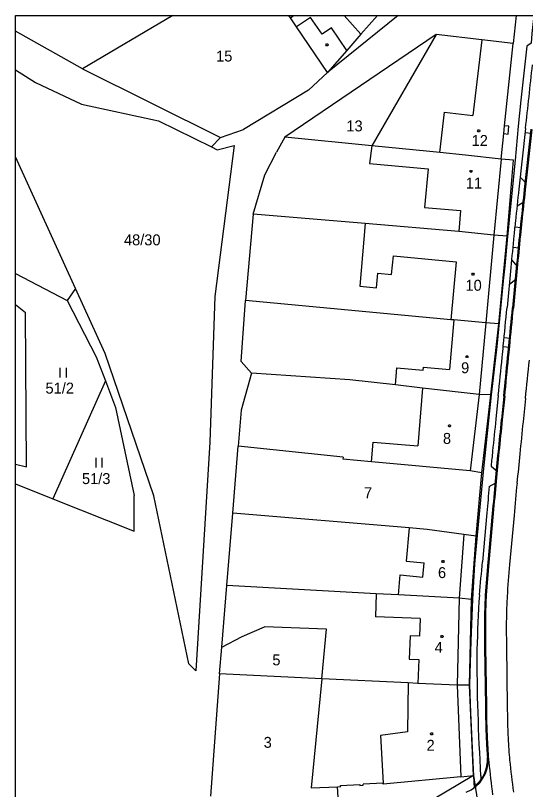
# Model space of a CAD drawing. Extents: x -639590 to -639298, y -1193269 to -1192863.
# Drawn here: x -639590.4 to -639511.2, y -1192983.6 to -1192863.3 of the extents above; entities that cross this region are included whole.
import ezdxf

# ---------------------------------------------------------------- set-up
doc = ezdxf.new("R2010")
doc.units = 0
for name, color, linetype in [('Vrstva 1', 7, 'Continuous'), ('Vrstva 19', 7, 'Continuous'), ('Vrstva 2', 7, 'Continuous'), ('Vrstva 20', 7, 'Continuous'), ('Vrstva 21', 7, 'Continuous'), ('Vrstva 3', 7, 'Continuous'), ('Vrstva 4', 7, 'Continuous'), ('Vrstva 5', 7, 'Continuous'), ('Vrstva 61', 7, 'Continuous')]:
    doc.layers.add(name, color=color, linetype=linetype)

msp = doc.modelspace()

# ---------------------------------------------------------------- linework, layer by layer
at = {"layer": 'Vrstva 1'}
for p, q in [((-639565.97, -1192863.27), (-639580, -1192871.57)), ((-639547.69, -1192863.63), (-639547.93, -1192863.27)), ((-639546.73, -1192865.04), (-639547.69, -1192863.63)), ((-639530.97, -1192863.27), (-639541.93, -1192872.12)), ((-639534.19, -1192863.27), (-639536.75, -1192866.15)), ((-639512.63, -1192863.27), (-639513.1, -1192867.65)), ((-639541.93, -1192872.12), (-639546.73, -1192865.04)), ((-639580, -1192871.57), (-639590.39, -1192865.7)), ((-639525.06, -1192866.23), (-639548.56, -1192882.19)), ((-639536.75, -1192866.15), (-639538.95, -1192868.69)), ((-639525.06, -1192866.23), (-639535.07, -1192883.53)), ((-639517.99, -1192867.05), (-639525.06, -1192866.23)), ((-639513.1, -1192867.65), (-639517.99, -1192867.05)), ((-639514.43, -1192880.41), (-639513.1, -1192867.65)), ((-639538.95, -1192868.69), (-639541.93, -1192872.12)), ((-639580, -1192871.57), (-639558.56, -1192882.23)), ((-639590.39, -1192871.73), (-639587.31, -1192873.7)), ((-639541.93, -1192872.12), (-639544.9, -1192874.86)), ((-639587.31, -1192873.7), (-639580.13, -1192877.06)), ((-639544.9, -1192874.86), (-639555, -1192880.97)), ((-639580.13, -1192877.06), (-639568.16, -1192879.64)), ((-639568.16, -1192879.64), (-639559.97, -1192883.7)), ((-639558.56, -1192882.23), (-639555, -1192880.97)), ((-639513.76, -1192880.48), (-639514.43, -1192880.41)), ((-639513.89, -1192881.71), (-639513.76, -1192880.48)), ((-639559.97, -1192883.7), (-639558.56, -1192882.23)), ((-639548.56, -1192882.19), (-639549.88, -1192884.53)), ((-639535.07, -1192883.53), (-639548.56, -1192882.19)), ((-639514.97, -1192885.59), (-639514.56, -1192881.64)), ((-639514.56, -1192881.64), (-639513.89, -1192881.71)), ((-639556.45, -1192883.48), (-639559.45, -1192906.94)), ((-639559.07, -1192884.15), (-639556.45, -1192883.48)), ((-639526.07, -1192884.42), (-639535.07, -1192883.53)), ((-639559.97, -1192883.7), (-639559.07, -1192884.15)), ((-639551.68, -1192888.03), (-639549.88, -1192884.53)), ((-639524.51, -1192884.57), (-639526.07, -1192884.42)), ((-639520.5, -1192884.97), (-639524.51, -1192884.57)), ((-639581.05, -1192905.73), (-639590.39, -1192885.22)), ((-639514.97, -1192885.59), (-639520.5, -1192884.97)), ((-639513.07, -1192885.76), (-639514.97, -1192885.59)), ((-639514.06, -1192897.59), (-639513.07, -1192885.76)), ((-639553.46, -1192894.18), (-639551.68, -1192888.03)), ((-639553.46, -1192894.18), (-639554.66, -1192907.58)), ((-639536.07, -1192895.63), (-639553.46, -1192894.18)), ((-639521.55, -1192896.85), (-639536.07, -1192895.63)), ((-639516.13, -1192897.41), (-639521.55, -1192896.85)), ((-639514.06, -1192897.59), (-639516.13, -1192897.41)), ((-639515.33, -1192911.2), (-639514.06, -1192897.59)), ((-639590.39, -1192903.36), (-639582.38, -1192907.56)), ((-639581.05, -1192905.73), (-639582.38, -1192907.56)), ((-639576.45, -1192915.83), (-639581.05, -1192905.73)), ((-639582.38, -1192907.56), (-639577.84, -1192916.35)), ((-639559.45, -1192906.94), (-639560.22, -1192929.6)), ((-639555.33, -1192917.06), (-639554.66, -1192907.58)), ((-639522.8, -1192910.56), (-639554.66, -1192907.58)), ((-639590.39, -1192908.18), (-639588.84, -1192909.43)), ((-639588.7, -1192933.43), (-639588.84, -1192909.43)), ((-639522.3, -1192910.61), (-639522.8, -1192910.56)), ((-639517.37, -1192911.07), (-639522.3, -1192910.61)), ((-639515.33, -1192911.2), (-639517.37, -1192911.07)), ((-639516.56, -1192922.27), (-639515.33, -1192911.2)), ((-639568.92, -1192937.95), (-639576.45, -1192915.83)), ((-639577.84, -1192916.35), (-639576.43, -1192920.08)), ((-639553.74, -1192918.86), (-639555.33, -1192917.06)), ((-639553.74, -1192918.86), (-639555.36, -1192924.62)), ((-639538.45, -1192919.9), (-639553.74, -1192918.86)), ((-639576.43, -1192920.08), (-639584.61, -1192938.41)), ((-639576.43, -1192920.08), (-639574.87, -1192924.21)), ((-639531.39, -1192920.71), (-639538.45, -1192919.9)), ((-639527.16, -1192921.19), (-639531.39, -1192920.71)), ((-639518.37, -1192922.19), (-639527.16, -1192921.19)), ((-639516.56, -1192922.27), (-639518.37, -1192922.19)), ((-639517.98, -1192934.38), (-639516.56, -1192922.27)), ((-639574.87, -1192924.21), (-639571.95, -1192937.9)), ((-639555.36, -1192924.62), (-639555.81, -1192930.2)), ((-639560.22, -1192929.6), (-639562.4, -1192965.13)), ((-639556.66, -1192940.65), (-639555.81, -1192930.2)), ((-639539.5, -1192931.94), (-639555.81, -1192930.2)), ((-639539.5, -1192931.94), (-639539.53, -1192932.24)), ((-639535.12, -1192932.64), (-639539.53, -1192932.24)), ((-639519.77, -1192934.05), (-639535.12, -1192932.64)), ((-639590.39, -1192933.02), (-639588.7, -1192933.43)), ((-639517.98, -1192934.38), (-639519.77, -1192934.05)), ((-639518.83, -1192944.22), (-639517.98, -1192934.38)), ((-639590.39, -1192936.1), (-639584.61, -1192938.41)), ((-639584.61, -1192938.41), (-639571.98, -1192943.45)), ((-639571.98, -1192943.45), (-639571.95, -1192937.9)), ((-639563.48, -1192964.08), (-639568.92, -1192937.95)), ((-639557.57, -1192951.91), (-639556.66, -1192940.65)), ((-639529.25, -1192942.94), (-639556.66, -1192940.65)), ((-639526.45, -1192943.17), (-639529.25, -1192942.94)), ((-639520.79, -1192943.95), (-639526.45, -1192943.17)), ((-639518.83, -1192944.22), (-639520.79, -1192943.95)), ((-639519.57, -1192954.08), (-639518.83, -1192944.22)), ((-639558.35, -1192961.49), (-639557.57, -1192951.91)), ((-639534.37, -1192953.17), (-639557.57, -1192951.91)), ((-639530.93, -1192953.36), (-639534.37, -1192953.17)), ((-639521.49, -1192953.87), (-639530.93, -1192953.36)), ((-639519.57, -1192954.08), (-639521.49, -1192953.87)), ((-639519.87, -1192967.38), (-639519.57, -1192954.08)), ((-639555.2, -1192959.79), (-639551.74, -1192958.33)), ((-639542.1, -1192958.67), (-639551.74, -1192958.33)), ((-639542.83, -1192966.4), (-639542.1, -1192958.67)), ((-639558.35, -1192961.49), (-639555.2, -1192959.79)), ((-639558.69, -1192965.64), (-639558.35, -1192961.49)), ((-639562.4, -1192965.13), (-639563.48, -1192964.08)), ((-639558.69, -1192965.64), (-639560.13, -1192984.63)), ((-639542.83, -1192966.4), (-639558.69, -1192965.64)), ((-639542.83, -1192966.4), (-639544.48, -1192983.34)), ((-639529.4, -1192967.04), (-639542.83, -1192966.4)), ((-639527.9, -1192967.11), (-639529.4, -1192967.04)), ((-639521.81, -1192967.4), (-639527.9, -1192967.11)), ((-639519.87, -1192967.38), (-639521.81, -1192967.4)), ((-639519.26, -1192981.41), (-639519.87, -1192967.38)), ((-639519.26, -1192981.41), (-639537.01, -1192991.95)), ((-639521.22, -1192981.65), (-639533.3, -1192982.79)), ((-639521.22, -1192981.65), (-639519.26, -1192981.41)), ((-639519.26, -1192981.41), (-639518.33, -1192987.4)), ((-639544.48, -1192983.34), (-639540.36, -1192983.16)), ((-639540.36, -1192983.16), (-639539.89, -1192983.14)), ((-639540.12, -1192987.45), (-639540.36, -1192983.16)), ((-639539.9, -1192982.97), (-639536.91, -1192982.81)), ((-639539.89, -1192983.14), (-639539.9, -1192982.97)), ((-639536.91, -1192982.81), (-639536.9, -1192982.97)), ((-639536.9, -1192982.97), (-639536.4, -1192982.94)), ((-639533.31, -1192982.61), (-639536.41, -1192982.78)), ((-639536.4, -1192982.94), (-639536.41, -1192982.78)), ((-639533.3, -1192982.79), (-639533.31, -1192982.61))]:
    msp.add_line(p, q, dxfattribs=at)
at = {"layer": 'Vrstva 19'}
for p, q in [((-639510.2, -1192880.97), (-639511.23, -1192890.36)), ((-639512.47, -1192902.55), (-639513.06, -1192908.75)), ((-639514.42, -1192922.47), (-639514.8, -1192926.12)), ((-639516.2, -1192940.69), (-639516.89, -1192948.32)), ((-639517.39, -1192961.4), (-639517.26, -1192970.67))]:
    msp.add_line(p, q, dxfattribs=at)
for points in [[(-639511.19, -1192922.8), (-639511.56, -1192926.45)], [(-639512.96, -1192940.98), (-639513.65, -1192948.61)], [(-639514.14, -1192961.35), (-639514.01, -1192970.63)]]:
    msp.add_lwpolyline(points, dxfattribs=at)
for centre, radius, start, end in [((-638527.12, -1192999.08), 990.09, 173.69574, 173.98604), ((-639011.24, -1192947.67), 503.25, 174.0319, 174.2845), ((-638472.17, -1193000.65), 1044.92, 174.33796, 174.61298), ((-641501.16, -1192720.81), 1996.96, 354.42773, 354.59962), ((-640505.63, -1192817.43), 996.75, 354.29543, 354.39908), ((-641546.01, -1192712.41), 2042.42, 354.09679, 354.26487), ((-641546.01, -1192712.41), 2045.67, 354.09679, 354.26487), ((-638039.17, -1193078.86), 1483.51, 174.09044, 174.28397), ((-638039.17, -1193078.86), 1480.26, 174.09044, 174.28397), ((-638765.76, -1193005.72), 753.25, 174.31453, 174.66566), ((-638765.76, -1193005.72), 750, 174.31453, 174.66566), ((-637998.74, -1193076.46), 1523.52, 174.69877, 174.88721), ((-637998.74, -1193076.46), 1520.27, 174.69877, 174.88721), ((-639366.3, -1192962.73), 151.28, 174.5256, 176.4609), ((-639366.3, -1192962.73), 148.03, 174.5256, 176.4609), ((-639439.16, -1192957.83), 78.25, 176.7658, 178.8764), ((-639440.28, -1192957.78), 73.88, 176.7498, 178.8924), ((-639362.14, -1192958.46), 155.28, 179.2067, 181.0911), ((-639362.14, -1192958.46), 152.03, 179.2067, 181.0911), ((-639365.99, -1192969.45), 151.28, 180.4545, 182.3898), ((-639365.99, -1192969.45), 148.03, 180.4545, 182.3898), ((-639438.97, -1192972.1), 78.25, 182.6947, 185.3222), ((-639438.97, -1192972.1), 75, 182.6947, 185.3222), ((-639366.33, -1192964.54), 151.28, 185.6271, 187.5624), ((-639366.33, -1192964.54), 148.03, 185.6271, 187.5624)]:
    msp.add_arc(centre, radius, start, end, dxfattribs=at)
at = {"layer": 'Vrstva 20'}
for p, q in [((-639511.19, -1192880.86), (-639512.22, -1192890.25)), ((-639510.35, -1192880.95), (-639511.37, -1192890.34)), ((-639511.26, -1192881.47), (-639510.26, -1192881.57)), ((-639512.02, -1192888.41), (-639511.11, -1192889.29)), ((-639512.5, -1192892.85), (-639511.43, -1192892.26)), ((-639512.85, -1192896.11), (-639511.85, -1192896.22)), ((-639513.17, -1192899.31), (-639512.17, -1192899.4)), ((-639513.35, -1192901.25), (-639512.45, -1192902.34)), ((-639513.47, -1192902.45), (-639514.06, -1192908.65)), ((-639512.62, -1192902.53), (-639513.21, -1192908.73)), ((-639513.72, -1192905.11), (-639512.63, -1192904.19)), ((-639514.51, -1192913.34), (-639513.51, -1192913.44)), ((-639514.64, -1192914.75), (-639513.65, -1192914.86)), ((-639515.41, -1192922.36), (-639515.79, -1192926.01)), ((-639514.57, -1192922.45), (-639514.94, -1192926.1)), ((-639516.52, -1192933.32), (-639515.6, -1192934.12)), ((-639516.82, -1192936.49), (-639515.77, -1192935.95)), ((-639517.2, -1192940.6), (-639517.88, -1192948.23)), ((-639516.35, -1192940.67), (-639517.04, -1192948.31)), ((-639517.54, -1192961.4), (-639517.41, -1192970.67)), ((-639519.27, -1192981.51), (-639519.16, -1192983.33)), ((-639518.15, -1192981.5), (-639518.1, -1192982.3))]:
    msp.add_line(p, q, dxfattribs=at)
for points in [[(-639509.9, -1192863.27), (-639510.19, -1192866.08), (-639510.33, -1192867.57), (-639510.97, -1192868.03), (-639511.91, -1192876.46), (-639512.33, -1192880.5), (-639512.79, -1192885.74)], [(-639512.79, -1192885.74), (-639513.99, -1192897.61), (-639514.41, -1192902.17), (-639514.64, -1192904.53), (-639515.66, -1192914.71), (-639516.51, -1192922.25), (-639517.78, -1192934.19), (-639518.2, -1192938.62), (-639518.71, -1192944.08), (-639519.1, -1192948.55), (-639519.43, -1192954.01), (-639519.68, -1192960.51), (-639519.86, -1192967.3), (-639519.72, -1192971.68), (-639519.27, -1192981.51)]]:
    msp.add_lwpolyline(points, dxfattribs=at)
for centre, radius, start, end in [((-642488.93, -1192552.83), 2995.76, 353.71357, 353.90455), ((-638527.12, -1192999.08), 991.09, 173.69574, 173.98604), ((-638527.12, -1192999.08), 990.24, 173.69574, 173.98604), ((-639011.24, -1192947.67), 504.25, 174.0319, 174.2845), ((-639011.24, -1192947.67), 503.4, 174.0319, 174.2845), ((-638472.17, -1193000.65), 1045.92, 174.33796, 174.61298), ((-638472.17, -1193000.65), 1045.07, 174.33796, 174.61298), ((-641501.16, -1192720.81), 1995.96, 354.42773, 354.59962), ((-641501.16, -1192720.81), 1996.81, 354.42773, 354.59962), ((-640505.63, -1192817.43), 995.75, 354.29543, 354.39908), ((-640505.63, -1192817.43), 996.6, 354.29543, 354.39908), ((-641546.01, -1192712.41), 2041.42, 354.09679, 354.26487), ((-641546.01, -1192712.41), 2042.27, 354.09679, 354.26487), ((-638039.17, -1193078.86), 1484.51, 174.09044, 174.28397), ((-638039.17, -1193078.86), 1483.66, 174.09044, 174.28397), ((-638765.76, -1193005.72), 754.25, 174.31453, 174.4911), ((-638765.76, -1193005.72), 753.4, 174.31453, 174.66566), ((-637998.74, -1193076.46), 1524.52, 174.73196, 174.88721), ((-637998.74, -1193076.46), 1523.67, 174.69877, 174.88721), ((-639821.62, -1192922.97), 304.79, 354.2821, 355.2512), ((-639366.3, -1192962.73), 151.43, 174.5256, 176.4609), ((-639098.66, -1192977.23), 420.37, 176.742, 177.9035), ((-639439.16, -1192957.83), 78.4, 176.7658, 178.8764), ((-639362.14, -1192958.46), 155.43, 179.2067, 181.0911), ((-639200.74, -1192962.01), 318.01, 179.9715, 183.514), ((-639365.99, -1192969.45), 151.43, 180.4545, 182.3898), ((-639438.97, -1192972.1), 78.4, 182.6947, 184.7646), ((-639522.44, -1192978.92), 5.35, 307.6142, 3.3126)]:
    msp.add_arc(centre, radius, start, end, dxfattribs=at)
at = {"layer": 'Vrstva 21'}
msp.add_arc((-639522.44, -1192978.92), 5.5, 291.9686, 3.3126, dxfattribs=at)
at = {"layer": 'Vrstva 3'}
for p, q in [((-639583.48, -1192918.05), (-639583.48, -1192919.55)), ((-639582.48, -1192919.55), (-639582.48, -1192918.05)), ((-639577.93, -1192932.02), (-639577.93, -1192933.52)), ((-639576.93, -1192933.52), (-639576.93, -1192932.02))]:
    msp.add_line(p, q, dxfattribs=at)
at = {"layer": 'Vrstva 4'}
for p, q in [((-639547.69, -1192863.63), (-639547.22, -1192863.27)), ((-639544.56, -1192863.57), (-639546.73, -1192865.04)), ((-639542.78, -1192866.2), (-639544.56, -1192863.57)), ((-639536.75, -1192866.15), (-639539.37, -1192863.27)), ((-639541.32, -1192865.21), (-639542.78, -1192866.2)), ((-639538.95, -1192868.69), (-639541.32, -1192865.21)), ((-639517.99, -1192867.05), (-639519.35, -1192878.82)), ((-639524.51, -1192884.57), (-639523.78, -1192878.31)), ((-639523.78, -1192878.31), (-639519.35, -1192878.82)), ((-639514.56, -1192881.64), (-639514.43, -1192880.41)), ((-639535.07, -1192883.53), (-639535.39, -1192886.3)), ((-639514.97, -1192885.59), (-639516.13, -1192897.41)), ((-639535.39, -1192886.3), (-639526.32, -1192887.09)), ((-639526.32, -1192887.09), (-639526.87, -1192893.1)), ((-639526.87, -1192893.1), (-639521.26, -1192893.61)), ((-639521.26, -1192893.61), (-639521.55, -1192896.85)), ((-639536.07, -1192895.63), (-639536.92, -1192905.37)), ((-639516.13, -1192897.41), (-639517.37, -1192911.07)), ((-639531.98, -1192903.52), (-639531.71, -1192900.63)), ((-639531.71, -1192900.63), (-639521.95, -1192901.55)), ((-639521.95, -1192901.55), (-639522.8, -1192910.56)), ((-639534.33, -1192905.61), (-639534.12, -1192903.32)), ((-639534.12, -1192903.32), (-639531.98, -1192903.52)), ((-639536.92, -1192905.37), (-639534.33, -1192905.61)), ((-639522.3, -1192910.61), (-639522.99, -1192918.33)), ((-639517.37, -1192911.07), (-639518.37, -1192922.19)), ((-639531.39, -1192920.71), (-639531.15, -1192918.05)), ((-639531.15, -1192918.05), (-639527.06, -1192918.41)), ((-639527.06, -1192918.41), (-639527.02, -1192917.96)), ((-639527.02, -1192917.96), (-639522.99, -1192918.33)), ((-639527.16, -1192921.19), (-639527.92, -1192930.18)), ((-639518.37, -1192922.19), (-639519.77, -1192934.05)), ((-639535.12, -1192932.64), (-639534.86, -1192929.59)), ((-639534.86, -1192929.59), (-639527.92, -1192930.18)), ((-639529.25, -1192942.94), (-639529.72, -1192948.11)), ((-639520.79, -1192943.95), (-639521.49, -1192953.87)), ((-639529.72, -1192948.11), (-639526.93, -1192948.37)), ((-639527.13, -1192950.57), (-639526.93, -1192948.37)), ((-639530.93, -1192953.36), (-639530.64, -1192950.25)), ((-639530.64, -1192950.25), (-639527.13, -1192950.57)), ((-639534.37, -1192953.17), (-639534.5, -1192956.77)), ((-639521.49, -1192953.87), (-639521.81, -1192967.4)), ((-639527.54, -1192957.02), (-639534.5, -1192956.77)), ((-639527.54, -1192957.02), (-639527.64, -1192959.74)), ((-639529.1, -1192959.69), (-639529.23, -1192963.36)), ((-639527.64, -1192959.74), (-639529.1, -1192959.69)), ((-639529.23, -1192963.36), (-639527.77, -1192963.41)), ((-639527.77, -1192963.41), (-639527.9, -1192967.11)), ((-639529.4, -1192967.04), (-639529.52, -1192974.62)), ((-639521.81, -1192967.4), (-639521.22, -1192981.65)), ((-639529.52, -1192974.62), (-639533.72, -1192975.2)), ((-639533.72, -1192975.2), (-639533.31, -1192982.61))]:
    msp.add_line(p, q, dxfattribs=at)
at = {"layer": 'Vrstva 5'}
for points in [[(-639541.91, -1192867.68), (-639541.82, -1192867.83), (-639541.91, -1192867.98), (-639542.09, -1192867.98), (-639542.18, -1192867.83), (-639542.09, -1192867.68)], [(-639518.35, -1192881.04), (-639518.26, -1192881.19), (-639518.35, -1192881.34), (-639518.53, -1192881.34), (-639518.62, -1192881.19), (-639518.53, -1192881.04)], [(-639519.57, -1192887.35), (-639519.48, -1192887.5), (-639519.57, -1192887.65), (-639519.75, -1192887.65), (-639519.84, -1192887.5), (-639519.75, -1192887.35)], [(-639519.24, -1192903.34), (-639519.15, -1192903.49), (-639519.24, -1192903.64), (-639519.42, -1192903.64), (-639519.51, -1192903.49), (-639519.42, -1192903.34)], [(-639520.18, -1192916.16), (-639520.09, -1192916.31), (-639520.18, -1192916.46), (-639520.36, -1192916.46), (-639520.45, -1192916.31), (-639520.36, -1192916.16)], [(-639522.9, -1192926.92), (-639522.81, -1192927.07), (-639522.9, -1192927.22), (-639523.08, -1192927.22), (-639523.17, -1192927.07), (-639523.08, -1192926.92)], [(-639523.9, -1192948), (-639523.81, -1192948.15), (-639523.9, -1192948.3), (-639524.08, -1192948.3), (-639524.17, -1192948.15), (-639524.08, -1192948)], [(-639524.05, -1192959.66), (-639523.96, -1192959.81), (-639524.05, -1192959.96), (-639524.23, -1192959.96), (-639524.32, -1192959.81), (-639524.23, -1192959.66)], [(-639525.69, -1192974.81), (-639525.6, -1192974.96), (-639525.69, -1192975.11), (-639525.87, -1192975.11), (-639525.96, -1192974.96), (-639525.87, -1192974.81)]]:
    msp.add_lwpolyline(points, close=True, dxfattribs=at)
at = {"layer": 'Vrstva 61'}
for points in [[(-639590.39, -1193268.77), (-639590.39, -1192863.27)], [(-639590.39, -1192863.27), (-639298.39, -1192863.27)]]:
    msp.add_lwpolyline(points, dxfattribs=at)

# ---------------------------------------------------------------- texts
at = {"layer": 'Vrstva 2'}
for s, p in [('15', (-639559.24, -1192870.43)), ('13', (-639539.01, -1192881.29)), ('12', (-639519.56, -1192883.56)), ('11', (-639520.46, -1192890.17)), ('48/30', (-639573.55, -1192899)), ('10', (-639520.51, -1192906.06)), ('9', (-639521.19, -1192918.89)), ('51/2', (-639585.73, -1192922.05)), ('8', (-639524.01, -1192929.87)), ('51/3', (-639580.07, -1192936.12)), ('7', (-639536.26, -1192938.32)), ('6', (-639524.78, -1192950.73)), ('4', (-639525.3, -1192962.35)), ('5', (-639550.5, -1192964.3)), ('3', (-639551.85, -1192977.12)), ('2', (-639526.55, -1192977.58))]:
    msp.add_text(s, height=1.7, dxfattribs=at).set_placement(p)

doc.saveas('drawing.dxf')
